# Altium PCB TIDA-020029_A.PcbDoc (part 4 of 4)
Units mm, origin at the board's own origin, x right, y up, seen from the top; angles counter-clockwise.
Board outline 267.5 x 53.5 mm, 2 copper layers (Top Layer, Bottom Layer), stack 1.575 mm thick; 255 components, 134 nets, 990 pads, 1977 vias.
Unrouted connection lines stored in the file: 9.
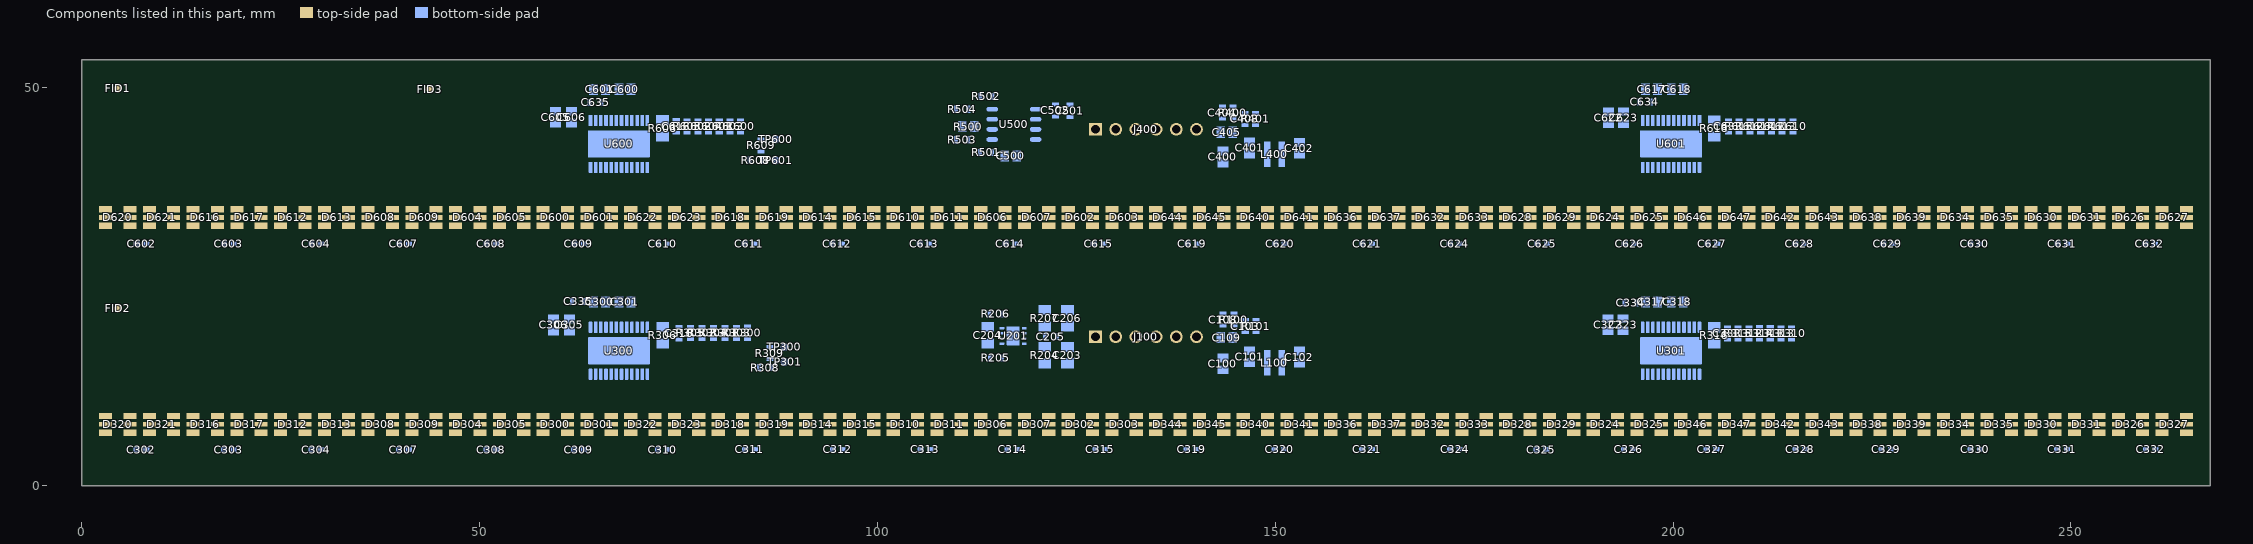
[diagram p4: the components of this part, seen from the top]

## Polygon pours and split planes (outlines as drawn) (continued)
NetD310_2 on Top Layer "TOP_LAYER_NETD310_2_P024" (solid, remove dead copper, pour order 24): 111.486,10.86 111.486,1.718 105.847,1.718 105.847,7.052 104.038,7.052 104.038,8.322 105.923,8.322 105.923,10.86
NetD314_2 on Top Layer "TOP_LAYER_NETD314_2_P022" (solid, remove dead copper, pour order 22): 100.486,10.86 100.486,1.718 94.847,1.718 94.847,7.052 92.964,7.052 92.964,8.322 94.923,8.322 94.923,10.86
1OUT0 on Top Layer "TOP_LAYER_1OUT0_P020" (solid, remove dead copper, pour order 20): 122.818,10.86 122.818,1.716 127.898,1.716 127.898,7.05 125.933,7.05 125.933,8.32 127.898,8.32 127.898,10.86
1OUT1 on Top Layer "TOP_LAYER_1OUT1_P018" (solid, remove dead copper, pour order 18): 111.818,10.86 111.818,1.716 116.898,1.716 116.898,7.05 114.859,7.05 114.859,8.32 116.898,8.32 116.898,10.86
1OUT2 on Top Layer "TOP_LAYER_1OUT2_P016" (solid, remove dead copper, pour order 16): 100.818,10.86 100.818,1.716 105.898,1.716 105.898,7.05 103.962,7.05 103.962,8.32 105.898,8.32 105.898,10.86
1OUT3 on Top Layer "TOP_LAYER_1OUT3_P014" (solid, remove dead copper, pour order 14): 89.818,10.86 89.818,1.716 94.898,1.716 94.898,7.05 92.939,7.05 92.939,8.32 94.898,8.32 94.898,10.86
1OUT4 on Top Layer "TOP_LAYER_1OUT4_P012" (solid, remove dead copper, pour order 12): 78.74,10.835 78.74,1.691 83.871,1.691 83.871,7.025 82.004,7.025 82.004,8.295 83.871,8.295 83.871,10.835
NetD318_2 on Top Layer "TOP_LAYER_NETD318_2_P010" (solid, remove dead copper, pour order 10): 89.408,10.835 89.408,1.692 84.074,1.692 84.074,7.026 82.004,7.026 82.004,8.296 84.074,8.296 84.074,10.835
NetD322_2 on Top Layer "TOP_LAYER_NETD322_2_P008" (solid, remove dead copper, pour order 8): 78.486,10.86 78.486,1.718 72.847,1.718 72.847,7.052 70.917,7.052 70.917,8.322 72.923,8.322 72.923,10.86
1OUT5 on Top Layer "TOP_LAYER_1OUT5_P006" (solid, remove dead copper, pour order 6): 67.818,10.86 67.818,1.716 72.898,1.716 72.898,7.05 70.712,7.05 70.712,8.32 72.898,8.32 72.898,10.86
GND on Bottom Layer "BOTTOM_LAYER_GND_P408" (solid, remove dead copper, pour order 408): 265.69,52.61 267.214,51.086 267.214,27.21 266.96,26.956 0.514,26.956 0.26,27.21 0.26,51.086 1.784,52.61
NetD626_2 on Bottom Layer "BOTTOM_LAYER_NETD626_2_P406" (solid, remove dead copper, pour order 406): 265.612,36.86 265.612,27.716 260.278,27.716 260.278,36.86
4OUT0 on Bottom Layer "BOTTOM_LAYER_4OUT0_P404" (solid, remove dead copper, pour order 404): 260.112,36.86 260.112,27.716 254.778,27.716 254.778,36.86
NetD630_2 on Bottom Layer "BOTTOM_LAYER_NETD630_2_P402" (solid, remove dead copper, pour order 402): 254.612,36.86 254.612,27.716 249.278,27.716 249.278,36.86
4OUT1 on Bottom Layer "BOTTOM_LAYER_4OUT1_P400" (solid, remove dead copper, pour order 400): 249.112,36.86 249.112,27.716 243.778,27.716 243.778,36.86
NetD634_2 on Bottom Layer "BOTTOM_LAYER_NETD634_2_P398" (solid, remove dead copper, pour order 398): 243.612,36.86 243.612,27.716 238.278,27.716 238.278,36.86
4OUT2 on Bottom Layer "BOTTOM_LAYER_4OUT2_P396" (solid, remove dead copper, pour order 396): 238.112,36.86 238.112,27.716 232.778,27.716 232.778,36.86
NetD638_2 on Bottom Layer "BOTTOM_LAYER_NETD638_2_P394" (solid, remove dead copper, pour order 394): 232.612,36.86 232.612,27.716 227.278,27.716 227.278,36.86
4OUT3 on Bottom Layer "BOTTOM_LAYER_4OUT3_P392" (solid, remove dead copper, pour order 392): 227.112,36.86 227.112,27.716 221.778,27.716 221.778,36.86
NetD642_2 on Bottom Layer "BOTTOM_LAYER_NETD642_2_P390" (solid, remove dead copper, pour order 390): 221.612,36.86 221.612,27.716 216.278,27.716 216.278,36.86
4OUT4 on Bottom Layer "BOTTOM_LAYER_4OUT4_P388" (solid, remove dead copper, pour order 388): 216.112,36.86 216.112,27.716 210.778,27.716 210.778,36.86
NetD646_2 on Bottom Layer "BOTTOM_LAYER_NETD646_2_P108" (solid, remove dead copper, pour order 108): 210.612,36.86 210.612,27.716 205.278,27.716 205.278,36.86
4OUT5 on Bottom Layer "BOTTOM_LAYER_4OUT5_P386" (solid, remove dead copper, pour order 386): 205.112,36.86 205.112,27.716 199.778,27.716 199.778,36.86
4OUT6 on Bottom Layer "BOTTOM_LAYER_4OUT6_P384" (solid, remove dead copper, pour order 384): 199.612,36.86 199.612,27.716 194.278,27.716 194.278,36.86
NetD624_1 on Bottom Layer "BOTTOM_LAYER_NETD624_1_P382" (solid, remove dead copper, pour order 382): 194.112,36.86 194.112,27.716 188.778,27.716 188.778,36.86
4OUT7 on Bottom Layer "BOTTOM_LAYER_4OUT7_P380" (solid, remove dead copper, pour order 380): 188.612,36.86 188.612,27.716 183.278,27.716 183.278,36.86
NetD628_1 on Bottom Layer "BOTTOM_LAYER_NETD628_1_P378" (solid, remove dead copper, pour order 378): 183.112,36.86 183.112,27.716 177.778,27.716 177.778,36.86
4OUT8 on Bottom Layer "BOTTOM_LAYER_4OUT8_P376" (solid, remove dead copper, pour order 376): 177.612,36.86 177.612,27.716 172.278,27.716 172.278,36.86
NetD632_1 on Bottom Layer "BOTTOM_LAYER_NETD632_1_P374" (solid, remove dead copper, pour order 374): 172.112,36.86 172.112,27.716 166.778,27.716 166.778,36.86
4OUT9 on Bottom Layer "BOTTOM_LAYER_4OUT9_P372" (solid, remove dead copper, pour order 372): 166.612,36.86 166.612,27.716 161.278,27.716 161.278,36.86
NetD636_1 on Bottom Layer "BOTTOM_LAYER_NETD636_1_P110" (solid, remove dead copper, pour order 110): 161.112,36.86 161.112,27.716 155.778,27.716 155.778,36.86
4OUT10 on Bottom Layer "BOTTOM_LAYER_4OUT10_P112" (solid, remove dead copper, pour order 112): 155.612,36.86 155.612,27.716 150.278,27.716 150.278,36.86
NetD640_1 on Bottom Layer "BOTTOM_LAYER_NETD640_1_P370" (solid, remove dead copper, pour order 370): 150.112,36.86 150.112,27.716 144.778,27.716 144.778,36.86
4OUT11 on Bottom Layer "BOTTOM_LAYER_4OUT11_P368" (solid, remove dead copper, pour order 368): 144.612,36.86 144.612,27.716 139.278,27.716 139.278,36.86
NetD644_1 on Bottom Layer "BOTTOM_LAYER_NETD644_1_P366" (solid, remove dead copper, pour order 366): 139.112,36.86 139.112,27.716 133.778,27.716 133.778,36.86
NetD602_2 on Bottom Layer "BOTTOM_LAYER_NETD602_2_P114" (solid, remove dead copper, pour order 114): 133.612,36.86 133.612,27.716 128.278,27.716 128.278,36.86
3OUT0 on Bottom Layer "BOTTOM_LAYER_3OUT0_P364" (solid, remove dead copper, pour order 364): 128.112,36.86 128.112,27.716 122.778,27.716 122.778,36.86
NetD606_2 on Bottom Layer "BOTTOM_LAYER_NETD606_2_P362" (solid, remove dead copper, pour order 362): 122.612,36.86 122.612,27.716 117.278,27.716 117.278,36.86
3OUT1 on Bottom Layer "BOTTOM_LAYER_3OUT1_P360" (solid, remove dead copper, pour order 360): 117.112,36.86 117.112,27.716 111.778,27.716 111.778,36.86
NetD610_2 on Bottom Layer "BOTTOM_LAYER_NETD610_2_P358" (solid, remove dead copper, pour order 358): 111.612,36.86 111.612,27.716 106.278,27.716 106.278,36.86
3OUT2 on Bottom Layer "BOTTOM_LAYER_3OUT2_P356" (solid, remove dead copper, pour order 356): 106.112,36.86 106.112,27.716 100.778,27.716 100.778,36.86
NetD614_2 on Bottom Layer "BOTTOM_LAYER_NETD614_2_P354" (solid, remove dead copper, pour order 354): 100.612,36.86 100.612,27.716 95.278,27.716 95.278,36.86
3OUT3 on Bottom Layer "BOTTOM_LAYER_3OUT3_P352" (solid, remove dead copper, pour order 352): 95.112,36.86 95.112,27.716 89.778,27.716 89.778,36.86
NetD618_2 on Bottom Layer "BOTTOM_LAYER_NETD618_2_P350" (solid, remove dead copper, pour order 350): 89.612,36.86 89.612,27.716 84.278,27.716 84.278,36.86
3OUT4 on Bottom Layer "BOTTOM_LAYER_3OUT4_P348" (solid, remove dead copper, pour order 348): 84.112,36.86 84.112,27.716 78.778,27.716 78.778,36.86
NetD622_2 on Bottom Layer "BOTTOM_LAYER_NETD622_2_P346" (solid, remove dead copper, pour order 346): 78.612,36.86 78.612,27.716 73.278,27.716 73.278,36.86
3OUT5 on Bottom Layer "BOTTOM_LAYER_3OUT5_P344" (solid, remove dead copper, pour order 344): 73.112,36.86 73.112,27.716 67.778,27.716 67.778,36.86
3OUT6 on Bottom Layer "BOTTOM_LAYER_3OUT6_P342" (solid, remove dead copper, pour order 342): 67.612,36.86 67.612,27.716 62.278,27.716 62.278,36.86
NetD600_1 on Bottom Layer "BOTTOM_LAYER_NETD600_1_P340" (solid, remove dead copper, pour order 340): 62.112,36.86 62.112,27.716 56.778,27.716 56.778,36.86
3OUT7 on Bottom Layer "BOTTOM_LAYER_3OUT7_P338" (solid, remove dead copper, pour order 338): 56.612,36.86 56.612,27.716 51.278,27.716 51.278,36.86
NetD604_1 on Bottom Layer "BOTTOM_LAYER_NETD604_1_P336" (solid, remove dead copper, pour order 336): 51.112,36.86 51.112,27.716 45.778,27.716 45.778,36.86
3OUT8 on Bottom Layer "BOTTOM_LAYER_3OUT8_P334" (solid, remove dead copper, pour order 334): 45.612,36.86 45.612,27.716 40.278,27.716 40.278,36.86
NetD608_1 on Bottom Layer "BOTTOM_LAYER_NETD608_1_P332" (solid, remove dead copper, pour order 332): 40.112,36.86 40.112,27.716 34.778,27.716 34.778,36.86
3OUT9 on Bottom Layer "BOTTOM_LAYER_3OUT9_P330" (solid, remove dead copper, pour order 330): 34.612,36.86 34.612,27.716 29.278,27.716 29.278,36.86
NetD612_1 on Bottom Layer "BOTTOM_LAYER_NETD612_1_P328" (solid, remove dead copper, pour order 328): 29.112,36.86 29.112,27.716 23.778,27.716 23.778,36.86
3OUT10 on Bottom Layer "BOTTOM_LAYER_3OUT10_P326" (solid, remove dead copper, pour order 326): 23.612,36.86 23.612,27.716 18.278,27.716 18.278,36.86
NetD616_1 on Bottom Layer "BOTTOM_LAYER_NETD616_1_P324" (solid, remove dead copper, pour order 324): 18.104,36.86 18.104,27.716 12.77,27.716 12.77,36.86
3OUT11 on Bottom Layer "BOTTOM_LAYER_3OUT11_P322" (solid, remove dead copper, pour order 322): 12.598,36.86 12.598,27.716 7.264,27.716 7.264,36.86
NetD620_1 on Bottom Layer "BOTTOM_LAYER_NETD620_1_P320" (solid, remove dead copper, pour order 320): 7.112,36.86 7.112,27.716 1.778,27.716 1.778,36.86
GND on Bottom Layer "BOTTOM_LAYER_GND_P318" (solid, remove dead copper, pour order 318): 265.83,25.862 267.208,24.484 267.208,0.608 266.954,0.354 0.508,0.354 0.254,0.608 0.254,24.484 1.632,25.862
NetD320_1 on Bottom Layer "BOTTOM_LAYER_NETD320_1_P316" (solid, remove dead copper, pour order 316): 7.112,10.868 7.112,1.724 1.778,1.724 1.778,10.868
1OUT11 on Bottom Layer "BOTTOM_LAYER_1OUT11_P314" (solid, remove dead copper, pour order 314): 12.598,10.868 12.598,1.724 7.264,1.724 7.264,10.868
NetD316_1 on Bottom Layer "BOTTOM_LAYER_NETD316_1_P312" (solid, remove dead copper, pour order 312): 18.161,10.868 18.161,1.724 12.827,1.724 12.827,10.868
1OUT10 on Bottom Layer "BOTTOM_LAYER_1OUT10_P204" (solid, remove dead copper, pour order 204): 23.698,10.868 23.698,1.724 18.364,1.724 18.364,10.868
NetD312_1 on Bottom Layer "BOTTOM_LAYER_NETD312_1_P202" (solid, remove dead copper, pour order 202): 29.21,10.868 29.21,1.724 23.876,1.724 23.876,10.868
1OUT9 on Bottom Layer "BOTTOM_LAYER_1OUT9_P200" (solid, remove dead copper, pour order 200): 34.696,10.868 34.696,1.724 29.362,1.724 29.362,10.868
NetD308_1 on Bottom Layer "BOTTOM_LAYER_NETD308_1_P198" (solid, remove dead copper, pour order 198): 40.132,10.868 40.132,1.724 34.798,1.724 34.798,10.868
1OUT8 on Bottom Layer "BOTTOM_LAYER_1OUT8_P196" (solid, remove dead copper, pour order 196): 45.695,10.868 45.695,1.724 40.361,1.724 40.361,10.868
NetD304_1 on Bottom Layer "BOTTOM_LAYER_NETD304_1_P194" (solid, remove dead copper, pour order 194): 51.181,10.868 51.181,1.724 45.847,1.724 45.847,10.868
1OUT7 on Bottom Layer "BOTTOM_LAYER_1OUT7_P192" (solid, remove dead copper, pour order 192): 56.642,10.868 56.642,1.724 51.308,1.724 51.308,10.868
NetD300_1 on Bottom Layer "BOTTOM_LAYER_NETD300_1_P190" (solid, remove dead copper, pour order 190): 62.23,10.868 62.23,1.724 56.896,1.724 56.896,10.868
1OUT6 on Bottom Layer "BOTTOM_LAYER_1OUT6_P188" (solid, remove dead copper, pour order 188): 67.691,10.868 67.691,1.724 62.357,1.724 62.357,10.868
1OUT5 on Bottom Layer "BOTTOM_LAYER_1OUT5_P186" (solid, remove dead copper, pour order 186): 73.152,10.868 73.152,1.724 67.818,1.724 67.818,10.868
NetD322_2 on Bottom Layer "BOTTOM_LAYER_NETD322_2_P184" (solid, remove dead copper, pour order 184): 78.613,10.868 78.613,1.724 73.279,1.724 73.279,10.868
1OUT4 on Bottom Layer "BOTTOM_LAYER_1OUT4_P182" (solid, remove dead copper, pour order 182): 84.201,10.868 84.201,1.724 78.867,1.724 78.867,10.868
NetD318_2 on Bottom Layer "BOTTOM_LAYER_NETD318_2_P180" (solid, remove dead copper, pour order 180): 89.586,10.868 89.586,1.724 84.252,1.724 84.252,10.868
1OUT3 on Bottom Layer "BOTTOM_LAYER_1OUT3_P178" (solid, remove dead copper, pour order 178): 95.174,10.868 95.174,1.724 89.84,1.724 89.84,10.868
NetD314_2 on Bottom Layer "BOTTOM_LAYER_NETD314_2_P176" (solid, remove dead copper, pour order 176): 100.584,10.868 100.584,1.724 95.25,1.724 95.25,10.868
1OUT2 on Bottom Layer "BOTTOM_LAYER_1OUT2_P174" (solid, remove dead copper, pour order 174): 106.172,10.868 106.172,1.724 100.838,1.724 100.838,10.868
NetD310_2 on Bottom Layer "BOTTOM_LAYER_NETD310_2_P172" (solid, remove dead copper, pour order 172): 111.654,10.868 111.654,1.724 106.32,1.724 106.32,10.868
1OUT1 on Bottom Layer "BOTTOM_LAYER_1OUT1_P170" (solid, remove dead copper, pour order 170): 117.094,10.868 117.094,1.724 111.76,1.724 111.76,10.868
NetD306_2 on Bottom Layer "BOTTOM_LAYER_NETD306_2_P168" (solid, remove dead copper, pour order 168): 122.555,10.868 122.555,1.724 117.221,1.724 117.221,10.868
1OUT0 on Bottom Layer "BOTTOM_LAYER_1OUT0_P116" (solid, remove dead copper, pour order 116): 128.143,10.868 128.143,1.724 122.809,1.724 122.809,10.868
NetD302_2 on Bottom Layer "BOTTOM_LAYER_NETD302_2_P166" (solid, remove dead copper, pour order 166): 133.604,10.868 133.604,1.724 128.27,1.724 128.27,10.868
NetD344_1 on Bottom Layer "BOTTOM_LAYER_NETD344_1_P164" (solid, remove dead copper, pour order 164): 139.065,10.868 139.065,1.724 133.731,1.724 133.731,10.868
2OUT11 on Bottom Layer "BOTTOM_LAYER_2OUT11_P162" (solid, remove dead copper, pour order 162): 144.653,10.868 144.653,1.724 139.319,1.724 139.319,10.868
NetD340_1 on Bottom Layer "BOTTOM_LAYER_NETD340_1_P160" (solid, remove dead copper, pour order 160): 150.114,10.868 150.114,1.724 144.78,1.724 144.78,10.868
2OUT10 on Bottom Layer "BOTTOM_LAYER_2OUT10_P158" (solid, remove dead copper, pour order 158): 155.702,10.868 155.702,1.724 150.368,1.724 150.368,10.868
NetD336_1 on Bottom Layer "BOTTOM_LAYER_NETD336_1_P156" (solid, remove dead copper, pour order 156): 161.239,10.868 161.239,1.724 155.905,1.724 155.905,10.868
2OUT9 on Bottom Layer "BOTTOM_LAYER_2OUT9_P154" (solid, remove dead copper, pour order 154): 166.624,10.868 166.624,1.724 161.29,1.724 161.29,10.868
NetD332_1 on Bottom Layer "BOTTOM_LAYER_NETD332_1_P152" (solid, remove dead copper, pour order 152): 171.958,10.868 171.958,1.724 166.624,1.724 166.624,10.868
2OUT8 on Bottom Layer "BOTTOM_LAYER_2OUT8_P150" (solid, remove dead copper, pour order 150): 177.546,10.868 177.546,1.724 172.212,1.724 172.212,10.868
NetD328_1 on Bottom Layer "BOTTOM_LAYER_NETD328_1_P148" (solid, remove dead copper, pour order 148): 183.134,10.868 183.134,1.724 177.8,1.724 177.8,10.868
2OUT7 on Bottom Layer "BOTTOM_LAYER_2OUT7_P146" (solid, remove dead copper, pour order 146): 188.722,10.868 188.722,1.724 183.388,1.724 183.388,10.868
NetD324_1 on Bottom Layer "BOTTOM_LAYER_NETD324_1_P144" (solid, remove dead copper, pour order 144): 194.056,10.868 194.056,1.724 188.722,1.724 188.722,10.868
2OUT6 on Bottom Layer "BOTTOM_LAYER_2OUT6_P142" (solid, remove dead copper, pour order 142): 199.644,10.868 199.644,1.724 194.31,1.724 194.31,10.868
2OUT5 on Bottom Layer "BOTTOM_LAYER_2OUT5_P140" (solid, remove dead copper, pour order 140): 205.232,10.868 205.232,1.724 199.898,1.724 199.898,10.868
NetD346_2 on Bottom Layer "BOTTOM_LAYER_NETD346_2_P138" (solid, remove dead copper, pour order 138): 210.566,10.868 210.566,1.724 205.232,1.724 205.232,10.868
2OUT4 on Bottom Layer "BOTTOM_LAYER_2OUT4_P136" (solid, remove dead copper, pour order 136): 216.154,10.868 216.154,1.724 210.82,1.724 210.82,10.868
NetD342_2 on Bottom Layer "BOTTOM_LAYER_NETD342_2_P134" (solid, remove dead copper, pour order 134): 221.488,10.868 221.488,1.724 216.154,1.724 216.154,10.868
2OUT3 on Bottom Layer "BOTTOM_LAYER_2OUT3_P132" (solid, remove dead copper, pour order 132): 227.076,10.868 227.076,1.724 221.742,1.724 221.742,10.868
NetD338_2 on Bottom Layer "BOTTOM_LAYER_NETD338_2_P130" (solid, remove dead copper, pour order 130): 232.41,10.868 232.41,1.724 227.076,1.724 227.076,10.868
2OUT2 on Bottom Layer "BOTTOM_LAYER_2OUT2_P128" (solid, remove dead copper, pour order 128): 237.998,10.868 237.998,1.724 232.664,1.724 232.664,10.868
NetD334_2 on Bottom Layer "BOTTOM_LAYER_NETD334_2_P126" (solid, remove dead copper, pour order 126): 243.584,10.868 243.584,1.724 238.25,1.724 238.25,10.868
2OUT1 on Bottom Layer "BOTTOM_LAYER_2OUT1_P124" (solid, remove dead copper, pour order 124): 249.174,10.868 249.174,1.724 243.84,1.724 243.84,10.868
NetD330_2 on Bottom Layer "BOTTOM_LAYER_NETD330_2_P122" (solid, remove dead copper, pour order 122): 254.676,10.87 254.676,1.726 249.342,1.726 249.342,10.87
2OUT0 on Bottom Layer "BOTTOM_LAYER_2OUT0_P120" (solid, remove dead copper, pour order 120): 260.096,10.868 260.096,1.724 254.762,1.724 254.762,10.868
NetD326_2 on Bottom Layer "BOTTOM_LAYER_NETD326_2_P118" (solid, remove dead copper, pour order 118): 265.43,10.868 265.43,1.724 260.096,1.724 260.096,10.868

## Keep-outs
Keep-Out Layer:
  text ".Layer_Name" at 14.656,-21.806 h1.52

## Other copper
Top Layer:
  text ".Layer_Name" at 14.656,-21.806 h1.52
Bottom Layer:
  text ".Layer_Name" at 14.656,-21.806 h1.52

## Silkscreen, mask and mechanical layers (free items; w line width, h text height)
Top Overlay:
  text "'.PRJ_Number'.PCB_Rev" at 13.36,45.695 h0.4
  text ".Layer_Name" at 14.656,-21.806 h0.4
Bottom Overlay:
  lines w0.254: 75.286,45.19 75.286,50.444 83.633,50.444 83.633,45.187 ; 75.971,19.612 75.971,24.867 84.319,24.867 84.319,19.609 ; 77.966,45.169 77.966,50.394 ; 78.652,19.592 78.652,24.816 ; 80.735,45.187 80.735,50.419 ; 81.421,19.609 81.421,24.841 ; 207.503,19.79 207.503,25.044 215.85,25.044 215.85,19.787 ; 207.62,46.079 207.62,51.333 215.967,51.333 215.967,46.076 ; 210.183,19.769 210.183,24.994 ; 210.3,46.058 210.3,51.283 ; 212.952,19.787 212.952,25.019 ; 213.069,46.076 213.069,51.308
  text "A0" at 209.423,50.292 h1.2
  text "A1" at 212.344,50.267 h1.2
  text "A2" at 215.011,50.267 h1.2
  text "A0" at 76.974,49.378 h1.2
  text "A1" at 79.895,49.352 h1.2
  text "A2" at 82.562,49.352 h1.2
  text "Hi  Lo" at 210.083,49.232 h1
  text "Hi  Lo" at 212.77,49.232 h1
  text "Hi  Lo" at 215.621,49.232 h1
  text "Vs" at 127.152,49.098 h1.5 r270
  text "LIN" at 129.657,49.098 h1.5 r270
  text "NC" at 132.193,49.098 h1.5 r270
  text "FS" at 134.714,49.098 h1.5 r270
  text "ERR" at 137.215,49.098 h1.5 r270
  text "GND" at 139.752,49.098 h1.5 r270
  text "Hi  Lo" at 77.753,48.203 h1
  text "Hi  Lo" at 80.496,48.203 h1
  text "Hi  Lo" at 83.315,48.203 h1
  text "A0" at 209.398,24.048 h1.2
  text "A1" at 212.319,24.023 h1.2
  text "A2" at 214.986,24.023 h1.2
  text "A0" at 77.851,23.842 h1.2
  text "A1" at 80.772,23.816 h1.2
  text "A2" at 83.439,23.816 h1.2
  text "Hi  Lo" at 209.954,23.038 h1
  text "Hi  Lo" at 212.674,23.038 h1
  text "Hi  Lo" at 215.519,23.038 h1
  text "Vs" at 127.096,23.012 h1.5 r270
  text "Hi  Lo" at 78.41,22.74 h1
  text "Hi  Lo" at 81.128,22.74 h1
  text "Hi  Lo" at 83.972,22.74 h1
  text "CANH" at 129.362,22.174 h1.5 r270
  text "CANL" at 131.978,22.174 h1.5 r270
  text "FS" at 134.595,22.174 h1.5 r270
  text "ERR" at 137.193,22.174 h1.5 r270
  text "GND" at 139.827,22.174 h1.5 r270
  text ".Layer_Name" at 14.656,-21.806 h1.52
Top Paste:
  text ".Layer_Name" at 14.656,-21.806 h1.52
Bottom Paste:
  text ".Layer_Name" at 14.656,-21.806 h1.52
Top Solder:
  text ".Layer_Name" at 14.656,-21.806 h1.52
  text ".Layer_Name" at 14.656,-21.806 h1.52
Bottom Solder:
  text ".Layer_Name" at 14.656,-21.806 h1.52
Drill Guide:
  text ".Layer_Name" at 14.656,-21.806 h1.52
M1 Board Outline:
  lines w0.254: 0,26.4 267.5,26.4 ; 0,0 0,53.5 267.5,53.5 267.5,0 0,0
  text ".Layer_Name" at 14.656,-21.806 h1.52
M2 Board Dimensions:
  rectangle: 0,-6.985 3.175,-3.81
  rectangle: 3.175,-10.16 12.7,-6.985
  lines w0.178: 0,-6.985 25.4,-6.985 ; 3.175,-10.16 3.175,-3.81 ; 6.35,-10.16 6.35,-3.81 ; 12.7,-10.16 12.7,-3.81 ; 19.05,-10.16 19.05,-3.81 ; 0,-10.16 25.4,-10.16 25.4,-3.81 0,-3.81 0,-10.16
  text ".Layer_Name" at 14.656,-21.806 h1.52
M3 3D STEP Top:
  text ".Layer_Name" at 14.656,-21.806 h1.52
M4 3D STEP Bottom:
  text ".Layer_Name" at 14.656,-21.806 h1.52
M5 Assembly Top:
  lines w0.254: -7.417,-23.626 160.223,-23.626 ; -7.417,-18.462 160.274,-18.462 ; -7.417,-13.297 -7.417,-28.791 94.31,-28.791 160.274,-28.791 160.274,-13.297 -7.404,-13.297 -7.404,-28.791 32.614,-28.791 ; 55.194,-28.791 55.194,-13.297 ; 87.376,-18.462 87.376,-13.297 ; 108.712,-18.462 108.712,-13.297 ; 124.511,-28.956 124.511,-23.804
  text "COMPONENTS MARKED 'DNP' SHOULD NOT BE POPULATED." at 29.299,-8.09 h1.52
  text "ASSEMBLY VARIANT:" at 29.286,-11.024 h1.52
  text ".VariantName" at 55.601,-11.024 h1.52
  text "PCB VIEWED FROM TOP SIDE" at -5.804,-16.654 h1.52
  text "BOARD #:" at 57.099,-16.654 h1.52
  text ".PRJ_Number" at 70.955,-16.654 h1.52
  text "REV:" at 92.405,-16.654 h1.52
  text ".PCB_Rev" at 99.809,-16.654 h1.52
  text "SVN REV:" at 113.69,-16.654 h1.52
  text ".VersionControl_RevNumber" at 126.543,-16.654 h1.52
  text "TID #:" at 57.099,-21.819 h1.52
  text ".TID" at 70.955,-21.819 h1.52
  text "PLOT NAME =" at -5.804,-27.034 h1.52
  text ".plot_File_Name" at 14.656,-27.034 h1.52
  text "GENERATED    :" at 57.15,-27.034 h1.52
  text ".Print_Date" at 79.235,-27.034 h1.52
  text ".Print_Time" at 97.752,-27.034 h1.52
  text "TEXAS INSTRUMENTS" at 129.87,-27.034 h1.52
M6 Assembly Bottom:
  lines w0.254: -7.429,-18.474 160.261,-18.474 ; -7.379,-23.639 160.261,-23.639 ; 28.334,-28.969 28.334,-23.817 ; 44.133,-18.474 44.133,-13.31 ; 65.468,-18.474 65.468,-13.31 ; 97.65,-28.804 97.65,-13.31 ; 120.231,-28.804 160.249,-28.804 160.249,-13.31 -7.429,-13.31 -7.429,-28.804 58.534,-28.804 160.261,-28.804 160.261,-13.31
  text "COMPONENTS MARKED 'DNP' SHOULD NOT BE POPULATED." at 154.991,-8.077 h1.52
  text ".VariantName" at 128.473,-11.024 h1.52
  text "ASSEMBLY VARIANT:" at 154.864,-11.024 h1.52
  text ".VersionControl_RevNumber" at 26.302,-16.667 h1.52
  text "SVN REV:" at 39.154,-16.667 h1.52
  text ".PCB_Rev" at 53.035,-16.667 h1.52
  text "REV:" at 60.439,-16.667 h1.52
  text ".PRJ_Number" at 81.89,-16.667 h1.52
  text "BOARD #:" at 95.745,-16.667 h1.52
  text "PCB VIEWED FROM BOTTOM SIDE" at 158.648,-16.667 h1.52
  text ".TID" at 81.89,-21.831 h1.52
  text "TID #:" at 95.745,-21.831 h1.52
  text "TEXAS INSTRUMENTS" at 22.974,-27.047 h1.52
  text ".Print_Time" at 55.093,-27.047 h1.52
  text ".Print_Date" at 73.609,-27.047 h1.52
  text "GENERATED    :" at 95.694,-27.047 h1.52
  text ".plot_File_Name" at 138.189,-27.047 h1.52
  text "PLOT NAME =" at 158.648,-27.047 h1.52
M9 Title Sheet:
  drawing of 57 lines, arcs and shapes, not listed
  text "1" at 18.792,204.127 h1.78
  text "2" at 82.182,204.127 h1.78
  text "3" at 145.411,204.127 h1.78
  text "4" at 209.08,204.127 h1.78
  text "5" at 272.555,204.127 h1.78
  text "6" at 336.182,204.127 h1.78
  text "A" at -10.579,175.095 h1.78
  text "A" at 365.341,175.095 h1.78
  text "B" at -10.579,114.643 h1.78
  text "B" at 365.341,114.643 h1.78
  text "C" at -10.579,54.318 h1.78
  text "C" at 365.341,54.318 h1.78
  text "PROJECT TITLE:" at 288.125,7.048 h1.14
  text ".PRJ_Title" at 289.395,3.662 h1.78
  text "DESIGNED FOR:" at 288.125,-0.597 h1.14
  text ".PRJ_Customer" at 289.395,-4.153 h1.78
  text "D" at -10.579,-5.88 h1.78
  text "D" at 365.341,-5.88 h1.78
  text "FILE NAME:" at 288.125,-8.217 h1.14
  text ".PCB_File_Name_No_Path" at 289.395,-11.265 h1.78
  text "Texas Instruments (TI) and/or its licensors do not warrant the accuracy or completeness of this specification" at 161.9,-15.376 h1.14
  text "ENGINEER:" at 288.125,-15.583 h1.14
  text "LAYOUT BY:" at 326.352,-15.583 h1.14
  text "or any information contained therein. TI and/or its licensors do not warrant that this design will meet" at 160.757,-18.237 h1.14
  text ".PRJ_Engineer" at 289.395,-19.52 h1.78
  text ".PCB_Layout" at 327.635,-19.52 h1.78
  text "the specifications, will be suitable for your application or fit for any particular purpose, or will operate in" at 160.757,-21.099 h1.14
  text ".Layer_Name" at 14.656,-21.806 h1.52
  text "ALTIUM DESIGNER VERSION:" at 326.352,-23.457 h1.14
  text "an implementation. TI and/or its licensors do not warrant that the design is production worthy. You should" at 160.757,-23.961 h1.14
  text "completely validate and test your design implementation to confirm the system functionality for your application." at 161.9,-26.822 h1.14
  text ".print_Scale" at 289.395,-26.843 h1.78
  text ".Application_BuildNumber" at 327.635,-26.843 h1.78
  text "1" at 18.792,-32.093 h1.78
  text "2" at 82.182,-32.093 h1.78
  text "3" at 145.411,-32.093 h1.78
  text "4" at 209.08,-32.093 h1.78
  text "5" at 272.555,-32.093 h1.78
  text "6" at 336.182,-32.093 h1.78
M10 Fab Notes:
  drawing of 189 lines, arcs and shapes, not listed
  text "DESIGN INFORMATION" at 314.503,161.447 h1.52
  text "MIN. TRACK WIDTH:" at 298.131,158.091 h1.52
  text "8" at 325.976,158.091 h1.52
  text "MIL" at 329.907,158.091 h1.52
  text "MIN. CLEARANCE:" at 298.131,154.938 h1.52
  text "0.2" at 324.452,154.938 h1.52
  text "mm" at 329.907,154.938 h1.52
  text "MIN. VIA PAD SIZE:" at 298.131,151.785 h1.52
  text "24" at 325.214,151.785 h1.52
  text "MIL" at 329.907,151.785 h1.52
  text "0.05mm (2MIL)" at 315.784,148.486 h1.52
  text "MINIMUM ANNULAR RING" at 289.769,148.277 h1.52
  text "EXTERNAL" at 333.768,148.277 h1.52
  text "PER" at 294.849,145.48 h1.52
  text "IPC-D-275 CLASS 2 LEVEL C" at 300.437,145.48 h1.52
  text "MIL, HOLES" at 338.238,142.928 h1.52
  text "+/-" at 328.27,142.709 h1.52
  text "+/-" at 349.961,142.709 h1.52
  text "REGISTRATION TOLERANCES:" at 289.769,142.682 h1.52
  text "METAL" at 320.243,142.682 h1.52
  text "5" at 334.879,142.683 h1.52
  text "3" at 356.037,142.683 h1.52
  text "MIL" at 358.99,142.682 h1.52
  text "HOLE SIZE TOLERANCE (UNLESS OTHERWISE SPECIFIED):" at 289.769,140.185 h1.52
  text "+/-" at 349.961,140.112 h1.52
  text "3" at 356.037,140.085 h1.52
  text "MIL" at 358.99,140.085 h1.52
  text "MATERIAL:" at 287.87,136.589 h1.52
  text "FR-4 High Tg" at 312.926,133.324 h1.52
  text "X" at 309.257,133.122 h1.52
  text "FR-408" at 298.563,133.007 h1.52
  text "OTHER" at 336.358,133.007 h1.52
  text "62 MIL (1.6mm) +/-10%" at 306.694,129.374 h1.52
  text "X" at 303.643,129.312 h1.52
  text "THICKNESS:" at 289.769,129.165 h1.52
  text "OTHER" at 339.33,129.165 h1.52
  text "TOLERANCE:" at 289.769,125.652 h1.52
  text "X" at 311.314,125.652 h1.52
  text "ANSI IPC-6012 TYPE 3 CLASS 2" at 315.836,125.652 h1.52
  text "OTHER +/-" at 315.835,121.989 h1.52
  text "BOW & TWIST:" at 289.769,118.302 h1.52
  text "X" at 311.314,118.302 h1.52
  text "ANSI IPC-6012 TYPE 3 CLASS 2" at 315.836,118.302 h1.52
  text "OTHER +/-" at 315.835,114.576 h1.52
  text "DRILLING:" at 287.87,111.258 h1.52
  text "NC_DRILL FILES" at 332.599,108.586 h1.52
  text "REFERENCE:" at 289.769,108.486 h1.52
  text "X" at 306.463,108.484 h1.52
  text "AS SHOWN" at 310.984,108.486 h1.52
  text "X" at 329.348,108.486 h1.52
  text "OTHER" at 340.168,104.873 h1.52
  text "PTH COPPER THICKNESS:" at 289.761,104.783 h1.52
  text "X" at 318.697,104.783 h1.52
  text "20-30 um" at 321.948,104.783 h1.52
  text "BOARD FINISH:" at 287.87,101.034 h1.52
  text "SILKSCREEN:" at 291.812,98.237 h1.52
  text "X" at 316.14,98.237 h1.52
  text "TOP" at 319.112,98.237 h1.52
  text "X" at 329.094,98.237 h1.52
  text "BOTTOM" at 332.091,98.237 h1.52
  text "SILKSCREEN COLOR:" at 291.812,94.295 h1.52
  text "X" at 316.115,94.295 h1.52
  text "WHITE" at 319.112,94.295 h1.52
  text "OTHER" at 332.091,94.295 h1.52
  text "X" at 319.442,90.652 h1.52
  text "GREEN" at 322.439,90.652 h1.52
  text "OTHER" at 338.136,90.652 h1.52
  text "SOLDER RESIST COLOR:" at 291.812,90.477 h1.52
  text "X" at 319.442,86.734 h1.52
  text "MATTE" at 322.439,86.734 h1.52
  text "SEMI-GLOSS" at 338.125,86.717 h1.52
  text "IMMERSION GOLD (ENIG)" at 314.819,82.345 h1.52
  text "ENEPIG" at 348.793,82.162 h1.52
  text "SURFACE FINISH:" at 287.87,82.136 h1.52
  text "X" at 310.298,82.136 h1.52
  text "IMM. TIN/SILVER OR EQUIV" at 296.24,78.649 h1.52
  text "OTHER" at 332.599,78.549 h1.52
  text "ARRAY/PANEL:" at 287.87,74.602 h1.52
  text "CUT AND TRIM PER M1 BOARD OUTLINE" at 314.819,74.393 h1.52
  text "N.C. ROUTE" at 314.819,70.94 h1.52
  text "X" at 332.295,70.94 h1.52
  text "V. SCORE" at 336.816,70.94 h1.52
  text "CERTIFICATION:" at 287.87,67.66 h1.52
  text "MATERIALS AND WORKMANSHIP FOR ALL PCBS" at 306.285,67.66 h1.52
  text "TO MEET OR EXCEED THE REQUIREMENTS OF:" at 306.285,65.271 h1.52
  text "X" at 297.078,62.003 h1.52
  text "ANSI IPC-A-600F CLASS ->" at 300.329,62.003 h1.52
  text "X" at 342.188,62.003 h1.52
  text "2" at 344.982,62.003 h1.52
  text "1" at 336.981,61.965 h1.52
  text "3" at 353.973,61.965 h1.52
  text "X" at 317.702,58.252 h1.52
  text "RoHS" at 320.953,58.252 h1.52
  text "OTHER" at 337.321,58.252 h1.52
  text "PER ORDER" at 347.407,58.252 h1.52
  text "ALL BOARDS MUST MEET OR EXCEED UL94-V0 REQUIREMENTS." at 288.569,54.345 h1.52
  text "PCB MUST BEAR THE UL94V-0 UL REGISTERED MATERIAL ID NUMBER" at 288.569,51.397 h1.52
  text "ADDITIONAL REQUIREMENTS:" at 287.87,47.094 h1.52
  text "MICROSECTION:" at 289.769,44.373 h1.52
  text "YES" at 312.775,44.373 h1.52
  text "REQUIRED" at 334.657,40.707 h1.52
  text "BARE BOARD ELEC. TEST:" at 289.769,40.634 h1.52
  text "NONE" at 322.935,40.634 h1.52
  text "X" at 331.66,40.634 h1.52
  text "PER ORDER" at 349.693,40.634 h1.52
  text "XX MIL VIAS REQUIRE NON-CONDUCTIVE FILL AND PLANARIZE" at 294.04,35.428 h1.5
  text "XX MIL VIAS REQUIRE CONDUCTIVE FILL AND PLANARIZE" at 294.243,32.787 h1.52
  text "OUTER XX MIL TRACES REQUIRE 50 OHM SINGLE-ENDED IMPEDANCE" at 294.218,28.637 h1.47
  text "LAYER 2 & 3 (INNER LAYERS) XX MIL WIDE, XX MIL SPACE / TRACES REQUIRE 100 OHM DIFFERENTIAL IMPEDANCE" at 294.015,22.65 h1.52
  text ".Layer_Name" at 14.656,-21.806 h1.52
M11 Gerber Information:
  lines w0.254: -7.417,-23.626 160.223,-23.626 ; -7.417,-18.462 160.274,-18.462 ; -7.417,-13.297 -7.417,-28.791 94.31,-28.791 160.274,-28.791 160.274,-13.297 -7.404,-13.297 -7.404,-28.791 32.614,-28.791 ; 55.194,-28.791 55.194,-13.297 ; 87.376,-18.462 87.376,-13.297 ; 108.712,-18.462 108.712,-13.297 ; 124.511,-28.956 124.511,-23.804
  text "ALL ARTWORK VIEWED FROM TOP SIDE" at -5.804,-16.654 h1.52
  text "BOARD #:" at 57.099,-16.654 h1.52
  text ".PRJ_Number" at 70.955,-16.654 h1.52
  text "REV:" at 92.405,-16.654 h1.52
  text ".PCB_Rev" at 99.809,-16.654 h1.52
  text "SVN REV:" at 113.69,-16.654 h1.52
  text ".VersionControl_RevNumber" at 126.543,-16.654 h1.52
  text "LAYER NAME =" at -5.804,-21.806 h1.52
  text "TID #:" at 57.099,-21.819 h1.52
  text ".TID" at 70.955,-21.819 h1.52
  text "PLOT NAME =" at -5.804,-27.034 h1.52
  text ".plot_File_Name" at 14.656,-27.034 h1.52
  text "GENERATED    :" at 57.15,-27.034 h1.52
  text ".Print_Date" at 79.235,-27.034 h1.52
  text ".Print_Time" at 97.752,-27.034 h1.52
  text "TEXAS INSTRUMENTS" at 129.87,-27.034 h1.52
M12 Stackup:
  drawing of 191 lines, arcs and shapes, not listed
  text "Layer" at 249.215,186.879 h1.52
  text "Name" at 259.626,186.879 h1.52
  text "Material" at 283.242,186.879 h1.52
  text "Thickness" at 305.08,186.879 h1.52
  text "Constant" at 321.586,186.879 h1.52
  text "Board Layer Stack" at 336.06,186.879 h1.52
  text "1" at 249.215,183.831 h1.52
  text "Top Overlay" at 259.626,183.831 h1.52
  text "2" at 249.215,180.783 h1.52
  text "Top Solder" at 259.626,180.783 h1.52
  text "Solder Resist" at 283.242,180.783 h1.52
  text "0.40mil" at 305.08,180.783 h1.52
  text "3.5" at 321.586,180.783 h1.52
  text "3" at 249.215,177.735 h1.52
  text "Top Layer" at 259.626,177.735 h1.52
  text "Copper" at 283.242,177.735 h1.52
  text "1.40mil" at 305.08,177.735 h1.52
  text "4" at 249.215,174.687 h1.52
  text "Dielectric1" at 259.626,174.687 h1.52
  text "FR-4" at 283.242,174.687 h1.52
  text "59.20mil" at 305.08,174.687 h1.52
  text "4.8" at 321.586,174.687 h1.52
  text "5" at 249.215,171.639 h1.52
  text "Bottom Layer" at 259.626,171.639 h1.52
  text "Copper" at 283.242,171.639 h1.52
  text "1.40mil" at 305.08,171.639 h1.52
  text "6" at 249.215,168.591 h1.52
  text "Bottom Solder" at 259.626,168.591 h1.52
  text "Solder Resist" at 283.242,168.591 h1.52
  text "0.40mil" at 305.08,168.591 h1.52
  text "3.5" at 321.586,168.591 h1.52
  text "7" at 249.215,165.543 h1.52
  text "Bottom Overlay" at 259.626,165.543 h1.52
  text ".Layer_Name" at 14.656,-21.806 h1.52
M13 Component Bodies Top:
  text ".Layer_Name" at 14.656,-21.806 h1.52
M14 Component Bodies Bottom:
  text ".Layer_Name" at 14.656,-21.806 h1.52
M15 Courtyards Top:
  text ".Layer_Name" at 14.656,-21.806 h1.52
M16 Courtyards Bottom:
  text ".Layer_Name" at 14.656,-21.806 h1.52
Drill Drawing:
  circle w0.254: c136.238,84.073 r0.702
  lines w0.254: 135.537,80.214 136.94,80.214 136.94,81.617 135.537,81.617 135.537,80.214 ; 135.537,87.932 136.94,87.932 136.238,86.529 135.537,87.932
  lines w0.305: 134.264,79.266 216.344,79.266 ; 134.264,88.739 216.344,88.739 ; 142.846,76.109 142.846,91.897 ; 151.279,76.109 151.279,91.897 ; 167.448,76.109 167.448,91.897 ; 174.03,76.109 174.03,91.897 ; 183.559,76.109 183.559,91.897 ; 201.957,76.109 201.957,91.897 ; 134.264,76.109 216.344,76.109 216.344,91.897 134.264,91.897 134.264,76.109
  text "Symbol" at 136.159,89.687 h1.83
  text "Quantity" at 143.793,89.687 h1.83
  text "Finished Hole Size" at 152.226,89.687 h1.83
  text "Plated" at 168.395,89.687 h1.83
  text "Hole Type" at 174.977,89.687 h1.83
  text "Drill Layer Pair" at 184.506,89.687 h1.83
  text "Hole Tolerance" at 202.904,89.687 h1.83
  text "96" at 143.793,86.529 h1.52
  text "7.87mil (0.200mm)" at 152.226,86.529 h1.52
  text "PTH" at 168.395,86.529 h1.52
  text "Round" at 174.977,86.529 h1.52
  text "Top Layer - Bottom Layer" at 184.506,86.529 h1.52
  text "1881" at 143.793,83.371 h1.52
  text "11.81mil (0.300mm)" at 152.226,83.371 h1.52
  text "PTH" at 168.395,83.371 h1.52
  text "Round" at 174.977,83.371 h1.52
  text "Top Layer - Bottom Layer" at 184.506,83.371 h1.52
  text "12" at 143.793,80.214 h1.52
  text "43.31mil (1.100mm)" at 152.226,80.214 h1.52
  text "PTH" at 168.395,80.214 h1.52
  text "Round" at 174.977,80.214 h1.52
  text "Top Layer - Bottom Layer" at 184.506,80.214 h1.52
  text "1989 Total" at 143.793,77.056 h1.52
  text ".Layer_Name" at 14.656,-21.806 h1.52
M17 Embedded Cavity:
  text ".Layer_Name" at 14.656,-21.806 h1.52
M18 Embedded Assembly:
  text ".Layer_Name" at 14.656,-21.806 h1.52
M19 Embedded Keepout:
  text ".Layer_Name" at 14.656,-21.806 h1.52

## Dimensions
0,-10.16 to 25.4,-10.16 on M2 Board Dimensions
0,0 to 0,53.5 on M2 Board Dimensions
0,0 to 267.5,0 on M2 Board Dimensions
